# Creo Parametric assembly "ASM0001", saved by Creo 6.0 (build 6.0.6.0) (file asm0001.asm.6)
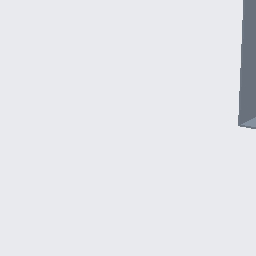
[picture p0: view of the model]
Units: Inch lbm Second (Pro/E Default); INCH, POUND, SECS

Created from: INLBS_ASM_DESIGN.ASM

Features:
  1. datum plane "ASM_RIGHT"
  2. datum plane "ASM_TOP"
  3. datum plane "ASM_FRONT"
  4. coordinate system
  5. component "PRT0001"
  6. component "LEFT"
  7. coordinate system
  8. component "BACK"
  9. component "PRT0002"
  10. component "RIGHT"

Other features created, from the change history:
  component "BACK.PRT"
  component "RIGHT.PRT"
  component "PRT0002.PRT"

Other named items: ACS4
